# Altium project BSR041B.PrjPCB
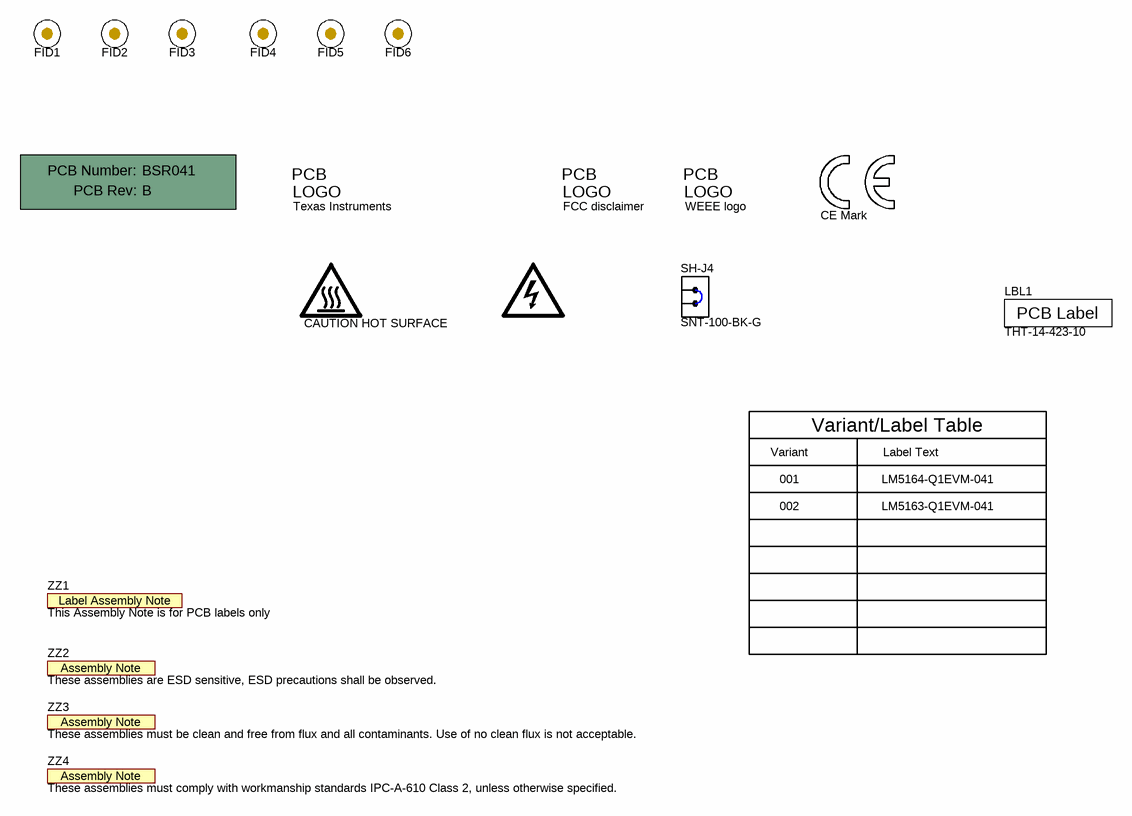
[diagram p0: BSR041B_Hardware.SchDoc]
CopyrightYear: 2018; PCB_Layout: Robert Loke; PCB_Rev: B; PRJ_Customer: INTERNAL; PRJ_Engineer: Brani Dubocanin; PRJ_Number: BSR041; PRJ_Title: LM5164-Q1 EVM Board; SCH_Rev: B; TechSupport: http://www.ti.com/support
2 sheets, 66 parts. Net scope: global (net labels, ports and power ports of the same name join across sheets).
Board file: BSR041B.PcbDoc
Sheets:
  BSR041B_Hardware.SchDoc
  BSR041B.SchDoc

## Sheet BSR041B_Hardware.SchDoc
size 431 x 279 mm; Date: Not shown in title block; ApprovedBy: Not shown in title block; CheckedBy: Not shown in title block; Author: Not shown in title block; CompanyName: Not shown in title block; Engineer: Not shown in title block; Organization: Not shown in title block; Address1: Not shown in title block; Address2: Not shown in title block; Address3: Not shown in title block; Address4: Not shown in title block; DocumentNumber: 1; Revision: Use project parameter SCH_Rev; SheetNumber: 1; SheetTotal: 1; PageSetup: Record=PageOptions¦CenterHorizontal=True¦CenterVertical=True¦PrintScale=1.00¦XCorrection=1.00¦YCorrection=1.00¦PrintKind=0¦BorderSize=5000000¦LeftOffset=0¦BottomOffset=0¦Orientation=2¦PaperLength=1000¦PaperWidth=1000¦Scale=100¦PaperSource=15¦PrintQuality=600¦MediaType=1¦DitherType=10¦PaperKind=Letter¦PrintScaleMode=1

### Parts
!PCB  Printed Circuit Board  (value not drawn)  (mechanical)
FID1  Fiducial  [Fiducial10-20]  (value not drawn)
FID2  Fiducial  [Fiducial10-20]  (value not drawn)
FID3  Fiducial  [Fiducial10-20]  (value not drawn)
FID4  Fiducial  [Fiducial10-20]  (value not drawn)
FID5  Fiducial  [Fiducial10-20]  (value not drawn)
FID6  Fiducial  [Fiducial10-20]  (value not drawn)
LBL1  THT-14-423-10  [Label_650x200]
Logo1  Texas Instruments  [TI_Stacked_Overlay_Small]  (no BOM)
Logo2  CE Mark  [CE_Mark_10mm]  (no BOM)
Logo3  FCC disclaimer  [FCC_disclaimer]  (no BOM)
Logo4  WEEE logo  [WEEE_Minimum]  (no BOM)
Logo5  DANGER HIGH VOLTAGE  [IEC_HighVoltage_Small]  (value not drawn)  (no BOM)
Logo6  CAUTION HOT SURFACE  [IEC_HotSurface_Small]  (no BOM)
SH-J4  SNT-100-BK-G  [SNT-100-BK-G]
ZZ1  This Assembly Note is for PCB labels only  [AssemblyNoteLabel]  (no BOM)
ZZ2  These assemblies are ESD sensitive, ESD precautions shall be observed.  [AssemblyNote]  (no BOM)
ZZ3  These assemblies must be clean and free from flux and all contaminants. Use of no clean flux is not acceptable.  [AssemblyNote]  (no BOM)
ZZ4  These assemblies must comply with workmanship standards IPC-A-610 Class 2, unless otherwise specified.  [AssemblyNote]  (no BOM)

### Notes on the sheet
- Variant/Label Table
- Variant
- 001
- Label Text
- LM5164-Q1EVM-041
- 002
- LM5163-Q1EVM-041

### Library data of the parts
!PCB = CMP-0003618-2: Manufacturer: Any; PartNumber: BSR041; CompType: PCB
FID1-FID6 = CMP-0077181-1: Fiducial mark.  There is nothing to buy or mount.
LBL1 = CMP-0003625-1: Thermal Transfer Printable Labels, 0.650" W x 0.200" H - 10,000 per roll; Manufacturer: Brady; Note: Size: 0.65" x 0.20 "
Logo1 = CMP-0074838-1: Texas Instrument Corporate Signature; SymbolCreator: a0412235; Lib Reference: TI_Logo; Library Reference: Logo
Logo2 = CMP-0074844-1: SymbolCreator: a0412235
Logo3 = CMP-0074847-1: FCC_disclaimer; Library Reference: Logo
Logo4 = CMP-0074769-1
Logo5 = CMP-0074835-1: IEC 61010-1 High Voltage Warning; SymbolCreator: a0412235
Logo6 = CMP-0074837-1: IEC 61010-1 Hot Surface Warning; SymbolCreator: a0412235
SH-J4 = CMP-0003623-1: Shunt, 100mil, Gold plated, Black; Alternate PartNumber: 969102-0000-DA; Manufacturer: Samtec; Alternate Manufacturer: 3M; Value: 1x2; Note: You can "mate" this to a header by matching the designator.  i.e. use SH-J3 for header J3
ZZ1 = CMP-0003616-3
ZZ2 = CMP-0077236-1
ZZ3 = CMP-0077237-1
ZZ4 = CMP-0077238-1

## Sheet BSR041B.SchDoc
size 431 x 279 mm; Date: Not shown in title block; ApprovedBy: Not shown in title block; CheckedBy: Not shown in title block; Author: Not shown in title block; CompanyName: Not shown in title block; Engineer: Not shown in title block; Organization: Not shown in title block; Address1: Not shown in title block; Address2: Not shown in title block; Address3: Not shown in title block; Address4: Not shown in title block; DocumentNumber: 1; Revision: Use project parameter SCH_Rev; SheetNumber: 1; SheetTotal: 1; PageSetup: Record=PageOptions¦CenterHorizontal=True¦CenterVertical=True¦PrintScale=1.00¦XCorrection=1.00¦YCorrection=1.00¦PrintKind=0¦BorderSize=5000000¦LeftOffset=0¦BottomOffset=0¦Orientation=2¦PaperLength=1000¦PaperWidth=1000¦Scale=100¦PaperSource=15¦PrintQuality=600¦MediaType=1¦DitherType=10¦PaperKind=Letter¦PrintScaleMode=1
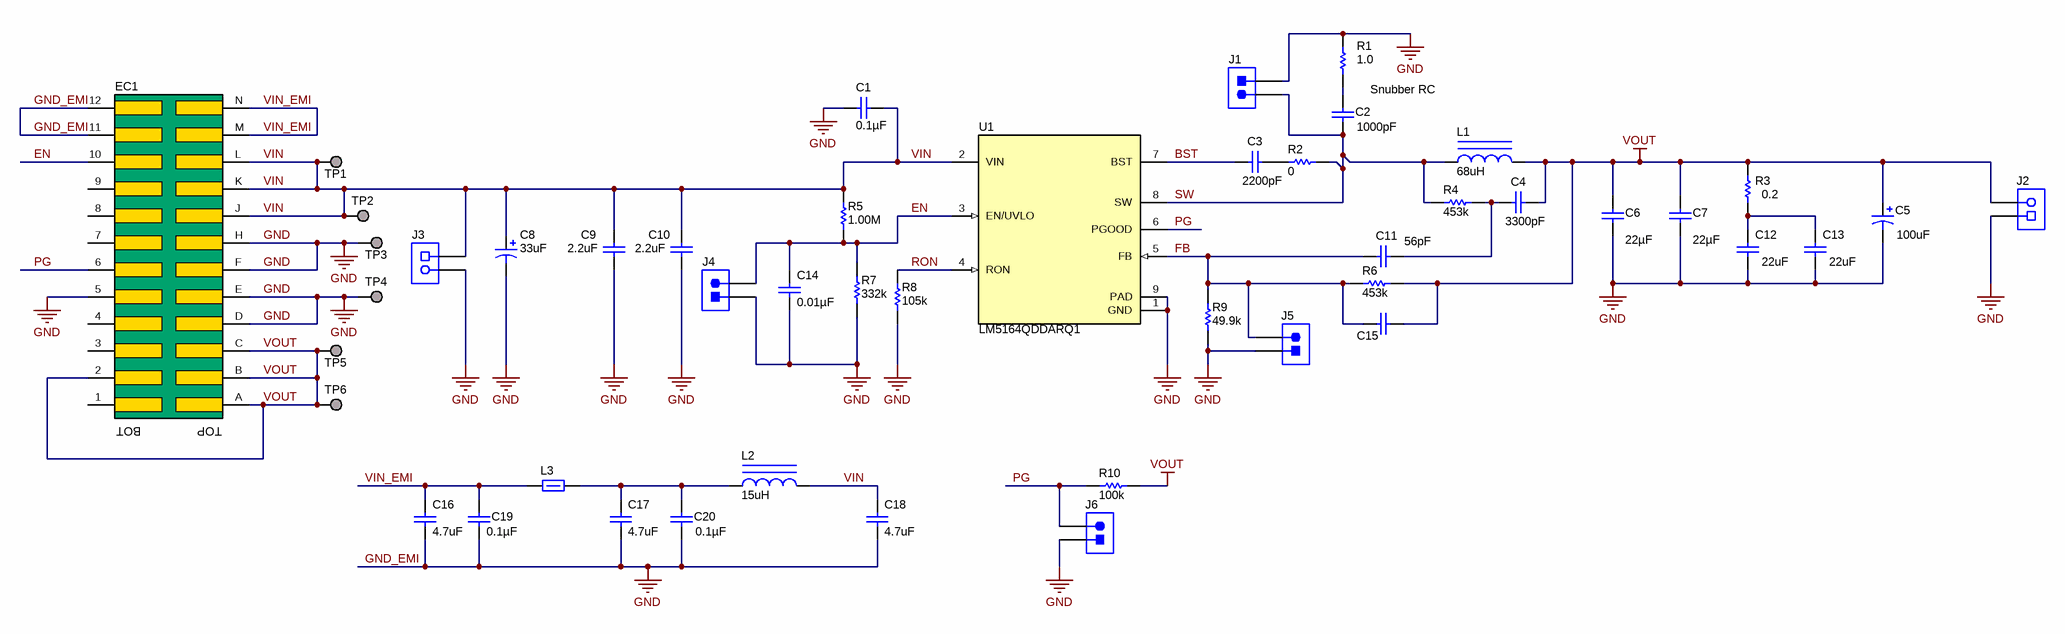
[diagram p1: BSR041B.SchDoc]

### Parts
C1  ValueDisplayed: 0.1µF  [0603_HV]  (hidden comment: HMK107B7104KAHT)
C2  ValueDisplayed: 1000pF  [0603L]  (hidden comment: CGA3E2X7R2A102K080AA)
C3  ValueDisplayed: 2200pF  [0402S]  (hidden comment: GCM155R71H222KA37D)
C4  ValueDisplayed: 3300pF  [0603L]  (hidden comment: CR)
C5  value 100uF  [Panasonic_D8]  (hidden comment: COUT_BULK)
C6  ValueDisplayed: 22µF  [1210_270L]  (hidden comment: GRT32ER61E226KE13L)
C7  ValueDisplayed: 22µF  [1210_270L]  (hidden comment: GRT32ER61E226KE13L)
C8  ValueDisplayed: 33uF  [SM_RADIAL_G]  (hidden comment: CIN_BULK)
C9  ValueDisplayed: 2.2uF  [1210_250L]  (hidden comment: CGA6N3X7R2A225K230AB)
C10  ValueDisplayed: 2.2uF  [1210_250L]  (hidden comment: CGA6N3X7R2A225K230AB)
C11  ValueDisplayed: 56pF  [0603L]  (hidden comment: C0603C560J5GACTU)
C12  value 22uF  [1210_270L]  (hidden comment: COUT3)
C13  value 22uF  [1210_270L]  (hidden comment: COUT4)
C14  ValueDisplayed: 0.01µF  [0603L]  (hidden comment: CEN)
C15  CFF  [0603L]  (value not drawn)
C16  ValueDisplayed: 4.7uF  [1210_220]  (hidden comment: CGA6M3X7S2A475K200AB)
C17  ValueDisplayed: 4.7uF  [1210_220]  (hidden comment: CGA6M3X7S2A475K200AB)
C18  ValueDisplayed: 4.7uF  [1210_220]  (hidden comment: CGA6M3X7S2A475K200AB)
C19  ValueDisplayed: 0.1µF  [0603_HV]  (hidden comment: HMK107B7104KAHT)
C20  ValueDisplayed: 0.1µF  [0603_HV]  (hidden comment: HMK107B7104KAHT)
EC1  Used in BOM report  [EDAC 12X2_AM]  (value not drawn)
J1  TSW-102-07-G-S  [TSW-102-07-G-S]  (value not drawn)
J2  ED555/2DS  [TERM_BLK_ED555-2DS]  (value not drawn)
J3  ED555/2DS  [TERM_BLK_ED555-2DS]  (value not drawn)
J4  TSW-102-07-G-S  [TSW-102-07-G-S]  (value not drawn)
J5  TSW-102-07-G-S  [TSW-102-07-G-S]  (value not drawn)
J6  TSW-102-07-G-S  [TSW-102-07-G-S]  (value not drawn)
L1  ValueDisplayed: 68uH  [MSS1246T]  (hidden comment: MSS1246T-683MLB)
L2  ValueDisplayed: 15uH  [MSS7341]  (hidden comment: MSS7341T-153MLB)
L3  FBMH3225HM202NT  [1210_280]  (value not drawn)
R1  ValueDisplayed: 1.0  [0603L]  (hidden comment: CRCW06031R00JNEA)
R2  ValueDisplayed: 0  [0402S]  (hidden comment: RBST)
R3  value 0.2  [2010]  (hidden comment: DNP)
R4  ValueDisplayed: 453k  [0603L]  (hidden comment: RC0603FR-07453KL)
R5  ValueDisplayed: 1.00M  [0603L]  (hidden comment: RC0603FR-071ML)
R6  ValueDisplayed: 453k  [0603L]  (hidden comment: RC0603FR-07453KL)
R7  ValueDisplayed: 332k  [0603L]  (hidden comment: RC0603FR-07332KL)
R8  ValueDisplayed: 105k  [0603L]  (hidden comment: RG1608P-1053-B-T5)
R9  ValueDisplayed: 49.9k  [0603]  (hidden comment: RG1608P-4992-B-T5)
R10  ValueDisplayed: 100k  [0402S]  (hidden comment: ERJ-2RKF1003X)
TP1  S1751-46  [Harwin_S1751-46]  (value not drawn)
TP2  (no value)  [Keystone1598-2]
TP3  (no value)  [Keystone1598-2]
TP4  (no value)  [Keystone1598-2]
TP5  (no value)  [Keystone1598-2]
TP6  S1751-46  [Harwin_S1751-46]  (value not drawn)
U1  LM5164QDDARQ1  [DDA0008E_L]

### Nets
GND: C1.1 C5.2(-) C6.2 C7.2 C8.2(-) C9.1 C10.1 C12.2 C13.2 C14.2 C16.2 C17.2 C18.2 C19.2 C20.2 EC1.5 EC1.11 EC1.12 EC1.D EC1.E EC1.F EC1.H J1.1 J2.1 J3.2 J4.1 J5.1 J6.1 R1.1 R7.1 R8.1 R9.1 TP3.1 TP4.1 U1.1(GND) U1.9(PAD)  [also labelled GND_EMI]
VOUT: C4.1 C5.1(+) C6.1 C7.1 C15.1 EC1.2 EC1.A EC1.B EC1.C J2.2 L1.2 R3.2 R6.2 R10.2 TP5.1 TP6.1
BST: C3.2 U1.7(BST)
EN: C14.1 EC1.10 J4.2 R5.1 R7.2 U1.3(EN/UVLO)
FB: C11.2 C15.2 J5.2 R6.1 R9.2 U1.5(FB)
PG: EC1.6 J6.2 R10.1 U1.6(PGOOD)
RON: R8.2 U1.4(RON)
SW: C2.1 J1.2 L1.1 R2.2 R4.1 U1.8(SW)
VIN: C1.2 C8.1(+) C9.2 C10.2 C18.1 EC1.J EC1.K EC1.L J3.1 L2.2 R5.2 TP1.1 TP2.1 U1.2(VIN)
VIN_EMI: C16.1 C19.1 EC1.M EC1.N L3.1
NetC2_2: C2.2 R1.2
NetC3_1: C3.1 R2.1
NetC4_2: C4.2 C11.1 R4.2
NetC12_1: C12.1 C13.1 R3.1
NetC17_1: C17.1 C20.1 L2.1 L3.2

Not connected (* = marked no-connect by the designer): EC1 1 3 4 7 8 9

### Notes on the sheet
- Snubber RC

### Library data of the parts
C1 C19 C20 = CMP-0081011-1: CAP, CERM, 0.1 µF, 100 V,+/- 10%, X7R, AEC-Q200 Grade 1, 0603; Manufacturer: Taiyo Yuden; TaMin_C: -55°C; Polarized: N; SizeAreaWB_mm2: 4.68; U/M: EA; Value: 0.1uF; TaMax_C: 125°C; SizeZ_mm: 1; SizeX_mm: 1.6; SizeY_mm: 0.8; Cap_Case: 0603; Value2: 100V; SizeArea_mm2: 1.28; CompType: Capacitor; AEC Qualified: Y; Cap_F: 100nF; AEC Category: Q200
C2 = CMP-0007081-4: CAP, CERM, 1000 pF, 100 V, +/- 10%, X7R, AEC-Q200 Grade 1, 0603; Manufacturer: TDK; TaMin_C: -55°C; ESR_ohm: 1.97137; Polarized: N; SizeAreaWB_mm2: 4.68; Value1: 1.97137 ohm; U/M: EA; Value: 1000pF; TaMax_C: 125°C; SizeZ_mm: 1; SizeX_mm: 1.6; SizeY_mm: 0.8; Cap_Case: 0603; Value2: 100V; SizeArea_mm2: 1.28; CompType: Capacitor; AEC Qualified: Y; Cap_F: 1nF; AEC Category: Q200; IRMS_A: 3.05705dA
C3 = CMP-0006357-2: CAP, CERM, 2200 pF, 50 V, +/- 10%, X7R, AEC-Q200 Grade 1, 0402; Manufacturer: MuRata; TaMin_C: -55°C; Polarized: N; SizeAreaWB_mm2: 3; Value1: Unknown; U/M: EA; Value: 2200pF; TaMax_C: 125°C; SizeZ_mm: 0.6; SizeX_mm: 1; SizeY_mm: 0.5; Cap_Case: 0402; Value2: 50V; CompType: Capacitor; AEC Qualified: Y; Cap_F: 2.2nF; AEC Category: Q200
C4 = CMP-0007087-4: CAP, CERM, 3300 pF, 100 V, +/- 10%, X7R, AEC-Q200 Grade 1, 0603; PartNumber: CGA3E2X7R2A332K080AA; Manufacturer: TDK; Polarized: N; CompType: Capacitor; Value: 3300pF; U/M: EA; Cap_F: 3.3nF; ESR_ohm: 6.62155d; Value1: 0.662155 ohm; VDC_V: 100V; IRMS_A: 3.0254dA; TaMin_C: -55°C; TaMax_C: 125°C; Cap_Case: 0603; SizeArea_mm2: 1.28; SizeAreaWB_mm2: 4.68; SizeX_mm: 1.6; SizeY_mm: 0.8; SizeZ_mm: 1; AEC Category: Q200; AEC Qualified: Y
C5 = CMP-0011205-2: CAP, AL, 100 uF, 50 V, +/- 20%, 0.34 ohm, AEC-Q200 Grade 2, SMD; PartNumber: EEEFTH101XAP; Manufacturer: Panasonic; Polarized: Y; CompType: Capacitor; U/M: EA; Cap_F: 100µF; VDC_V: 50V; ESR_ohm: 3.4d; IRMS_A: 3.5dA; TaMin_C: -55°C; TaMax_C: 105°C; Cap_Case: 6.3x7.7mm; SizeAreaWB_mm2: 73.96; SizeArea_mm2: 43.56; SizeX_mm: 6.6; SizeZ_mm: 8; AEC Category: Q200; AEC Grade: 2
C6 C7 = CMP-0084059-1: CAP, CERM, 22 µF, 25 V,+/- 10%, X5R, AEC-Q200 Grade 3, 1210; Manufacturer: MuRata; SizeAreaWB_mm2: 14.7; SizeArea_mm2: 8; AEC Qualified: Y; AEC Category: Q200; Value: 22uF; TaMax_C: 85°C; SizeZ_mm: 2.7; AEC Grade: 3; Polarized: N; TaMin_C: -55°C; VDC_V: 25V; SizeY_mm: 2.5; U/M: EA; CompType: Capacitor; SizeX_mm: 3.2; Cap_Case: 1210
C8 = CMP-0011203-2: CAP, AL, 33 uF, 100 V, +/- 20%, 0.7 ohm, AEC-Q200 Grade 2, SMD; PartNumber: EEE-FK2A330P; Manufacturer: Panasonic; Polarized: Y; CompType: Capacitor; Value: 33uF; U/M: EA; Cap_F: 33µF; Value1: 0.7 ohm; VDC_V: 100V; ESR_ohm: 7d; IRMS_A: 2dA; TaMin_C: -55°C; TaMax_C: 105°C; Cap_Case: G; SizeAreaWB_mm2: 172.2; SizeArea_mm2: 123.6; SizeX_mm: 12; SizeY_mm: 10.3; SizeZ_mm: 10.2; AEC Category: Q200; AEC Grade: 2
C9 C10 = CMP-0009152-2: CAP, CERM, 2.2 uF, 100 V, +/- 10%, X7R, AEC-Q200 Grade 1,; Manufacturer: TDK; Polarized: N; CompType: Capacitor; Value: 2.2uF; U/M: EA; Cap_F: 2.2µF; ESR_ohm: 1.73m; Value1: 0.00173 ohm; VDC_V: 100V; IRMS_A: 5.59317A; TaMin_C: -55°C; TaMax_C: 125°C; Cap_Case: 1210_250; AEC Category: Q200; AEC Qualified: Y; AEC Grade: 1; SizeArea_mm2: 8; SizeAreaWB_mm2: 14.7; SizeX_mm: 3.2; SizeY_mm: 2.5
C11 = CMP-0006952-4: CAP, CERM, 56 pF, 50 V, +/- 5%, C0G/NP0, 0603; Manufacturer: Kemet; TaMin_C: -55°C; Polarized: N; SizeAreaWB_mm2: 4.68; Value1: Unknown; U/M: EA; Value: 56pF; TaMax_C: 125°C; SizeZ_mm: 1; SizeX_mm: 1.6; SizeY_mm: 0.8; Cap_Case: 0603; Value2: 50V; SizeArea_mm2: 1.28; CompType: Capacitor; AEC Category: Q200
C12 C13 = CMP-0009255-2: CAP, CERM, 22 uF, 25 V, +/- 10%, X7R, AEC-Q200 Grade 1, 1210; PartNumber: TMK325B7226KMHT; Manufacturer: Taiyo Yuden; Polarized: N; CompType: Capacitor; U/M: EA; Cap_F: 22µF; Value1: Unknown; VDC_V: 25V; TaMin_C: -55°C; TaMax_C: 125°C; Cap_Case: 1210; AEC Category: Q200; AEC Qualified: Y; AEC Grade: 1; SizeArea_mm2: 8; SizeAreaWB_mm2: 14.7; SizeX_mm: 3.2; SizeY_mm: 2.5; SizeZ_mm: 2.7
C14 = CMP-0080063-1: CAP, CERM, 0.01 µF, 100 V,+/- 10%, X8R, AEC-Q200 Grade 0, 0603; Manufacturer: TDK; PartNumber: CGA3E2X8R2A103K080AD; TaMin_C: -55°C; Polarized: N; SizeAreaWB_mm2: 4.68; U/M: EA; Value: 0.01uF; TaMax_C: 150°C; SizeZ_mm: 1; SizeX_mm: 1.6; SizeY_mm: 0.8; Cap_Case: 0603; Value2: 100V; SizeArea_mm2: 1.28; CompType: Capacitor; AEC Qualified: Y; Cap_F: 10nF; AEC Grade: 0; AEC Category: Q200
C15 = CMP-0006844-4: CAP, CERM, 1000 pF, 50 V, +/- 5%, X7R, AEC-Q200 Grade 1, 0603; Manufacturer: Kemet; PartNumber: C0603C102J5RACAUTO; TaMin_C: -55°C; Polarized: N; SizeAreaWB_mm2: 4.68; Value1: Unknown; U/M: EA; Value: 1000pF; TaMax_C: 125°C; SizeZ_mm: 1; SizeX_mm: 1.6; SizeY_mm: 0.8; Cap_Case: 0603; Value2: 50V; SizeArea_mm2: 1.28; CompType: Capacitor; AEC Qualified: Y; Cap_F: 1nF; AEC Category: Q200
C16-C18 = CMP-0009150-2: CAP, CERM, 4.7 uF, 100 V, +/- 10%, X7S, AEC-Q200 Grade 1, 1210; Manufacturer: TDK; TaMin_C: -55°C; ESR_ohm: 4.236m; Polarized: N; SizeAreaWB_mm2: 14.7; Value1: 0.004236 ohm; U/M: EA; Value: 4.7uF; TaMax_C: 125°C; SizeZ_mm: 2.2; SizeX_mm: 3.2; SizeY_mm: 2.5; Value2: 100V; SizeArea_mm2: 8; CompType: Capacitor; AEC Qualified: Y; Cap_F: 4.7µF; IRMS_A: 3.57337A; AEC Grade: 1; AEC Category: Q200
EC1 = EDAC 12X2_AM: EDAC 12X2 24-Contact Dual Sided Edge Connector Feature; SymbolVersion: use current date i.e. 2008-05-20; SymbolCreator: Use a-id; CompType: Used in some BOM reports.  Useful for finding later.; U/M: EA, IN, or GM
J1 J4-J6 = CMP-0075405-2: Header, 100mil, 2x1, Gold, TH; Manufacturer: Samtec; Current_A: 6.3A; Green_Lifecycle: Active; Shrouded: N; Gender: Male; Green_REACh: Passed; Voltage_V: 550V; Row_Count: 1; Pitch_mm: 2.54; Cert_UL: Y
J2 J3 = CMP-0074913-1: Terminal Block, 3.5mm Pitch, 2x1, TH; Manufacturer: On-Shore Technology; Cert_VDE: Y; CNHeader: False; Current_A: 6A; Green_Lifecycle: Active; Shrouded: N; Gender: Female; Green_REACh: Passed; Voltage_V: 150V; Row_Count: 1; Pitch_mm: 3.5; ContactFinish: Brass; CT: True
L1 = CMP-0061481-2: Inductor, Shielded Drum Core, Ferrite, 68 uH, 1.8 A, 0.17 ohm, SMD; Manufacturer: Coilcraft; Value: 68uH; Ind_H: 68µH; Imax_A: 1.8A; Irms: 1.8A @ 40C rise; Isat: 2.74A @ 30% inductance drop; DCR_ohm: 1.7d; SizeAreaWB_mm2: 196; SizeArea_mm2: 144; SizeX_mm: 12; SizeZ_mm: 4.6; AEC Category: Q200; Green_Lifecycle: Not Set; Green_REACh: Incomplete
L2 = CMP-0061601-2: Inductor, Shielded Drum Core, Ferrite, 15 uH, 1.8 A, 0.05 ohm, AEC-Q200 Grade 1, SMD; Manufacturer: Coilcraft; Isat: 1.8A @ 30% inductance drop; Irms: 3A @ 40C rise; Green_Lifecycle: Not Set; SizeAreaWB_mm2: 86.49; DCR_ohm: 0.05; Green_REACh: Incomplete; Value: 15uH; Imax_A: 1.8A; SizeZ_mm: 4.1; SizeX_mm: 7.3; SizeArea_mm2: 53.29; Ind_H: 15µH; AEC Qualified: Y; AEC Grade: 1; AEC Category: Q200
L3 = CMP-0003373-1: Ferrite Bead, 2000 ohm @ 100 MHz, 1.2 A, 1210; Manufacturer: Taiyo Yuden; ZTyp@100MHz_Ohm: 2k; SizeAreaWB_mm2: 14.7; DCR_ohm: 1.3d; Value1: 0.13 ohm; Imax_A: 1.2A; SizeZ_mm: 2.8; SizeX_mm: 3.2; SizeY_mm: 2.5; SizeArea_mm2: 8
R1 = CMP-0025743-4: RES, 1.0, 5%, 0.1 W, AEC-Q200 Grade 0, 0603; Manufacturer: Vishay-Dale; Power_W: 100mW; TempCo: 200 ppm/C; Value_Code: 1R00; Value: 1.0; EIA_Code: E24; Res_ohm: 1; SizeX_mm: 1.6; SizeY_mm: 0.8; Value2: 0.1W; SizeArea_mm2: 1.28; CompType: Resistor; AEC Qualified: Y; VDC_V: 75V; AEC Category: Q200; AEC Grade: 0
R2 = CMP-0026822-3: RES, 0, 5%, 0.063 W, AEC-Q200 Grade 0, 0402; Manufacturer: Vishay-Dale; PartNumber: CRCW04020000Z0ED; Power_W: 63mW; TempCo: 200 ppm/C; Value_Code: 0000; Value: 0; EIA_Code: E24; SizeX_mm: 1; SizeY_mm: 0.5; SizeZ_mm: 0.6; Value2: 0.063W; CompType: Resistor; AEC Qualified: Y; VDC_V: 50V; AEC Category: Q200
R3 = CMP-0016525-2: RES, 0.2, 1%, 1 W, 2010; Manufacturer: Stackpole Electronics Inc; PartNumber: CSRN2010FKR200; Power_W: 1W; TempCo: 250 ppm/C; Value_Code: R200; U/M: EA; EIA_Code: E96; Res_ohm: 2d; SizeX_mm: 5; SizeY_mm: 2.5; SizeZ_mm: 1.66; SizeArea_mm2: 12.5; CompType: Resistor; AEC Category: Q200
R4 R6 = CMP-0023120-4: RES, 453 k, 1%, 0.1 W, 0603; Manufacturer: Yageo; Power_W: 100mW; TempCo: 100 ppm/C; Value: 453k; EIA_Code: E96; SizeX_mm: 1.6; SizeY_mm: 0.8; SizeZ_mm: 1; Value2: 0.1W; SizeArea_mm2: 1.28; CompType: Resistor; AEC Qualified: N; VDC_V: 75V; AEC Category: Q200; SizeAreaWB_mm2: 4.68
R5 = CMP-0022899-4: RES, 1.00 M, 1%, 0.1 W, 0603; Manufacturer: Yageo; Power_W: 100mW; TempCo: 100 ppm/C; Value_Code: 1M00; Value: 1.00Meg; EIA_Code: E96; Res_ohm: 1M; SizeX_mm: 1.6; SizeY_mm: 0.8; SizeZ_mm: 1; Value2: 0.1W; SizeArea_mm2: 1.28; CompType: Resistor; AEC Qualified: N; VDC_V: 75V; AEC Category: Q200; SizeAreaWB_mm2: 4.68
R7 = CMP-0023034-4: RES, 332 k, 1%, 0.1 W, 0603; Manufacturer: Yageo; Power_W: 100mW; TempCo: 100 ppm/C; Value: 332k; EIA_Code: E96; SizeX_mm: 1.6; SizeY_mm: 0.8; SizeZ_mm: 1; Value2: 0.1W; SizeArea_mm2: 1.28; CompType: Resistor; AEC Qualified: N; VDC_V: 75V; AEC Category: Q200; SizeAreaWB_mm2: 4.68
R8 = CMP-0023408-3: RES, 105 k, 0.1%, 0.1 W, 0603; Manufacturer: Susumu Co Ltd; Power_W: 100mW; TempCo: 25 ppm/C; U/M: EA; Value: 105k; EIA_Code: E192; SizeX_mm: 1.6; SizeY_mm: 0.8; SizeZ_mm: 1; Value2: 0.1W; SizeArea_mm2: 1.28; CompType: Resistor; VDC_V: 75V; AEC Category: Q200
R9 = CMP-0023563-3: RES, 49.9 k, 0.1%, 0.1 W, 0603; Manufacturer: Susumu Co Ltd; Power_W: 100mW; TempCo: 25 ppm/C; Value_Code: 49k9; U/M: EA; Value: 49.9k; EIA_Code: E192; SizeX_mm: 1.6; SizeY_mm: 0.8; SizeZ_mm: 1; Value2: 0.1W; SizeArea_mm2: 1.28; CompType: Resistor; VDC_V: 75V; AEC Category: Q200
R10 = CMP-0026659-1: RES, 100 k, 1%, 0.1 W, 0402; Manufacturer: Panasonic; Power_W: 100mW; TempCo: 100 ppm/C; U/M: EA; Value: 100k; EIA_Code: E96; SizeX_mm: 1; SizeY_mm: 0.5; SizeZ_mm: 0.6; Value2: 0.1W; CompType: Resistor; VDC_V: 50V; AEC Category: Q200
TP1 TP6 = CMP-0075188-1: Test Lead clips and hooks, SMT; Manufacturer: Harwin; CNHeader: False; Current_A: 2A; CompType: Test Point; ContactFinish: Tin; CT: True
TP2-TP5 = 1598-2: Terminal, Turret, TH, Triple; Manufacturer: Keystone; CompType: Turret Terminal; U/M: EA
U1 = CMP-0080796-1: 100-V Low IQ Synchronous Buck Regulator, DDA0008E (SOIC-8); Alternate PartNumber: LM5164QDDATQ1; Alternate Manufacturer: Texas Instruments; SizeAreaWB_mm2: 57.4; SizeZ_mm: 1.7; SizeX_mm: 5; SizeY_mm: 6.2; SizeArea_mm2: 31; CompType: IC; AEC Qualified: Y; AEC Category: Q200

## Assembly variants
001: not fitted C5 C12 C13 C14 C15 EC1 FID1 FID2 FID3 FID4 FID5 FID6 J1 J4 J5 R1 R3
002: not fitted C5 C7 C12 C13 C14 C15 EC1 FID1 FID2 FID3 FID4 FID5 FID6 J1 J4 J5 R1 R3; alternate parts L1 -> CMP-0061895-2, R4 -> CMP-0022218-4, U1 -> CMP-0860118-1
